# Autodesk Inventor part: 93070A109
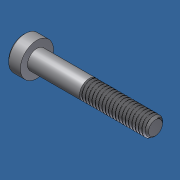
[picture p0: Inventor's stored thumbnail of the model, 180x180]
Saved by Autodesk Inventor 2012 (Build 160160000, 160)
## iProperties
Created: 2016-09
Part Number: 93070A109
Material: Default
Document SubType Name: Modeling
Designer: Admin
Density: 1 g/cm^3
Author: Admin
Translation Standard: STEP AP203
FileName: 93070A109.step
PreProcessor: SolidWorks 2010
PostProcessor: Build: 160, Release: 2012 RTM - Date: Tue 03/01/2011
Sent Units: inch
Uncertainty: 1e-05
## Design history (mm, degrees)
feature "Base1"
node "Cut-Extrude2"
